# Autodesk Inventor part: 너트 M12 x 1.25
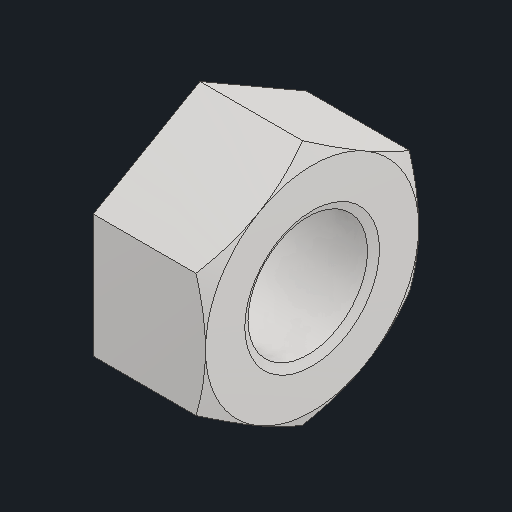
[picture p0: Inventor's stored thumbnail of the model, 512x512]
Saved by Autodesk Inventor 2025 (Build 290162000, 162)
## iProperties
Created: 2025-08
Part Number: 너트 M12 x 1.25
Material: 스테인리스강
Description: 6각 너트
Document SubType Name: Modeling
Designer: infra08
Density: 8.08 g/cm^3
Appearance: 기본값
Author: jhkim
Sending System: Autodesk Inventor 2026
Preprocessor: ST-DEVELOPER v20.1
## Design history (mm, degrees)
feature "Solid1"
node "솔리드1"
